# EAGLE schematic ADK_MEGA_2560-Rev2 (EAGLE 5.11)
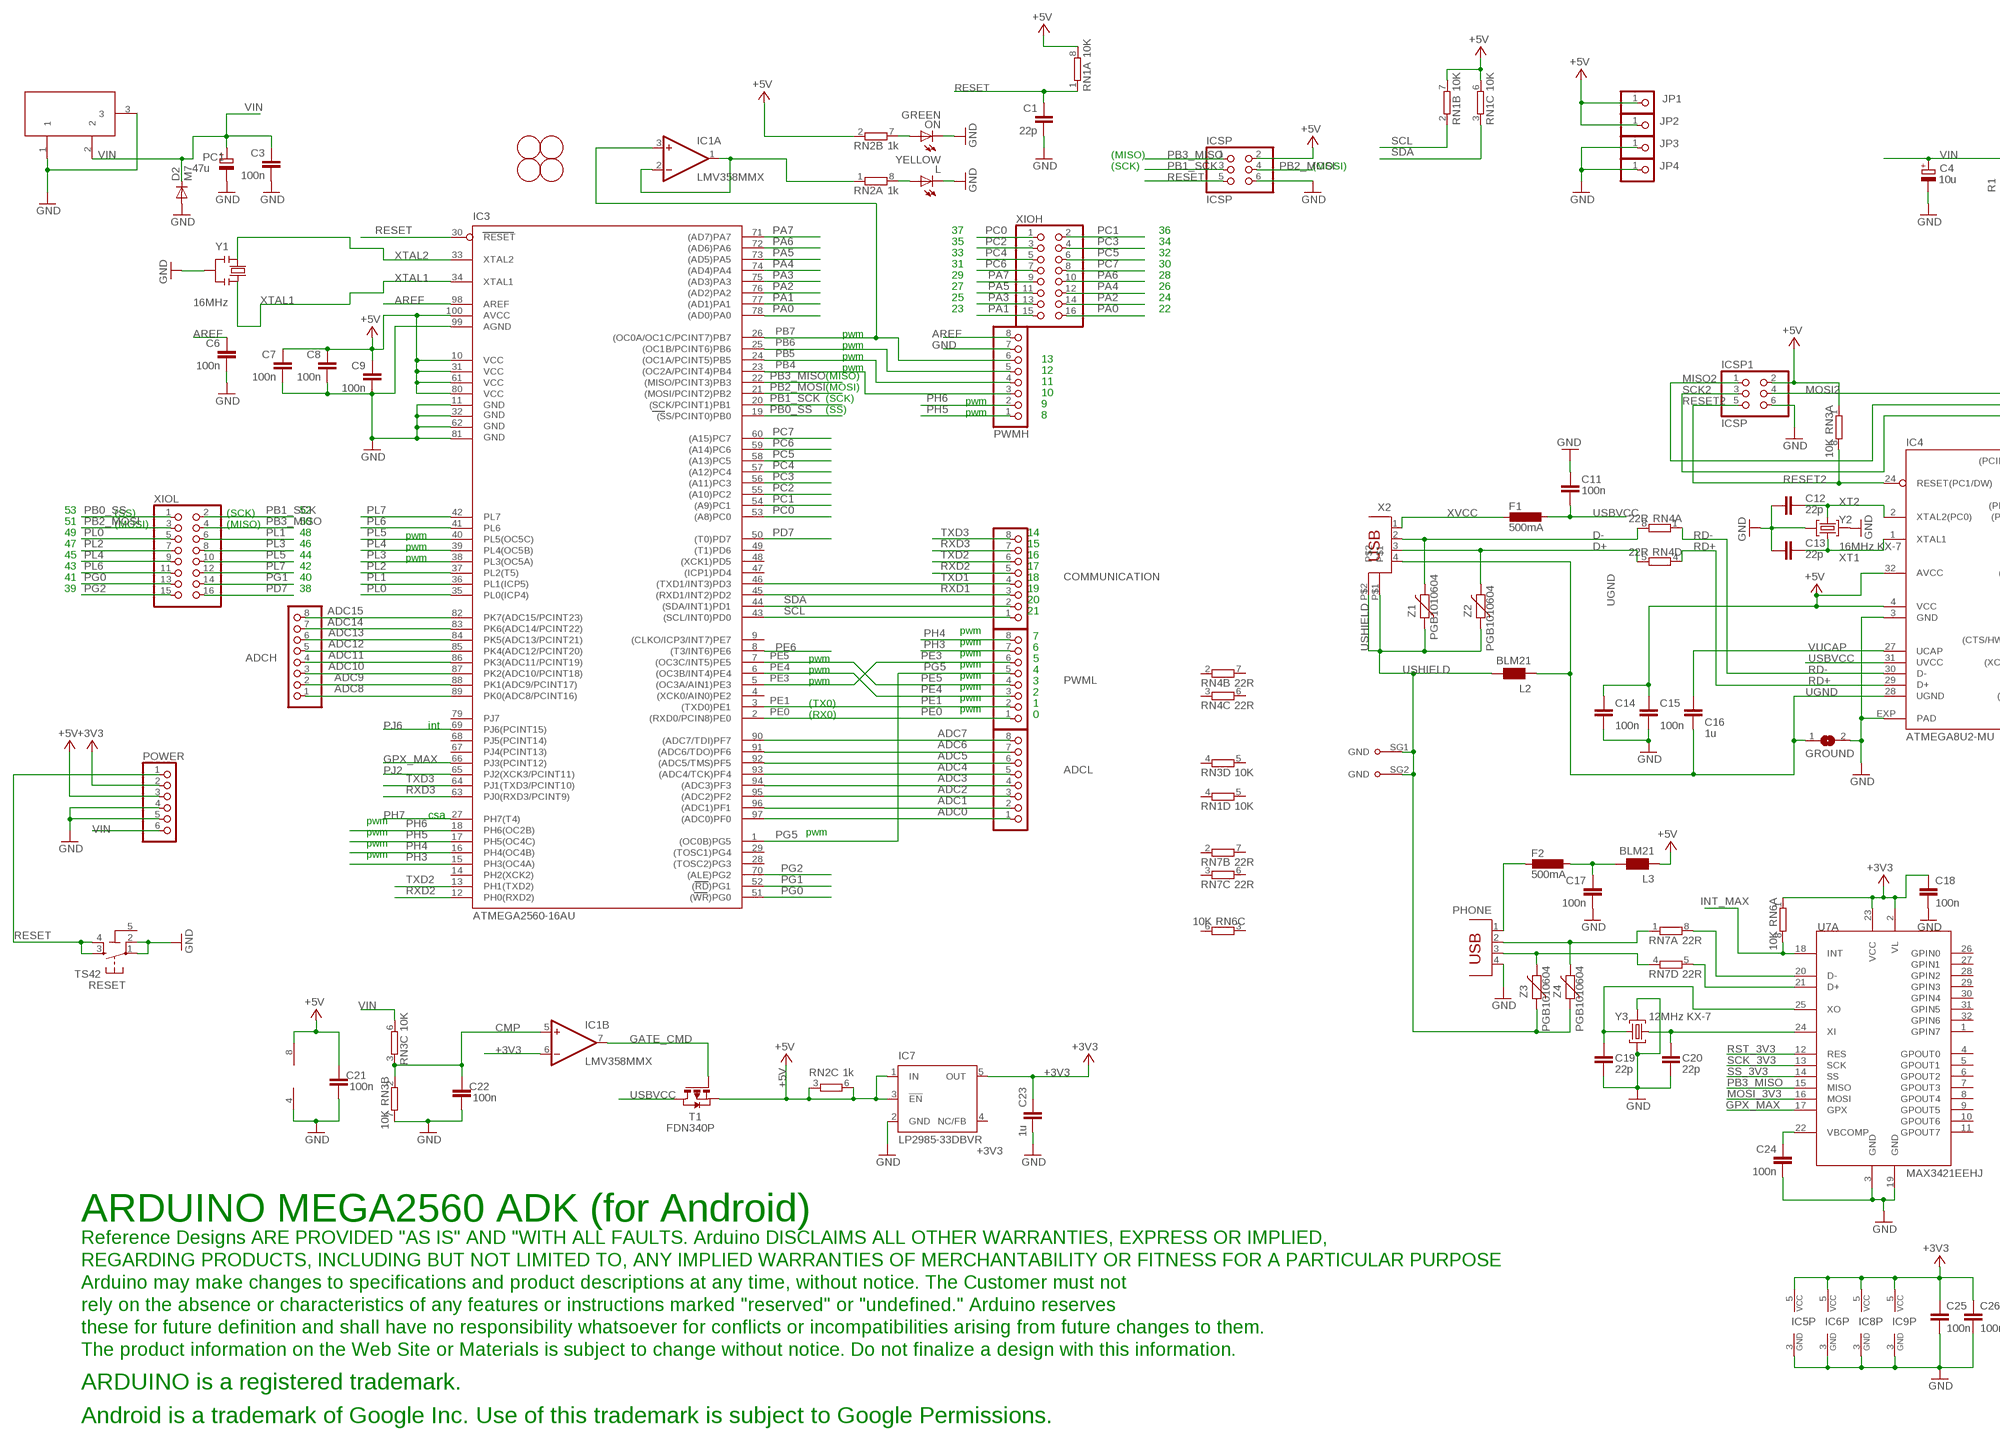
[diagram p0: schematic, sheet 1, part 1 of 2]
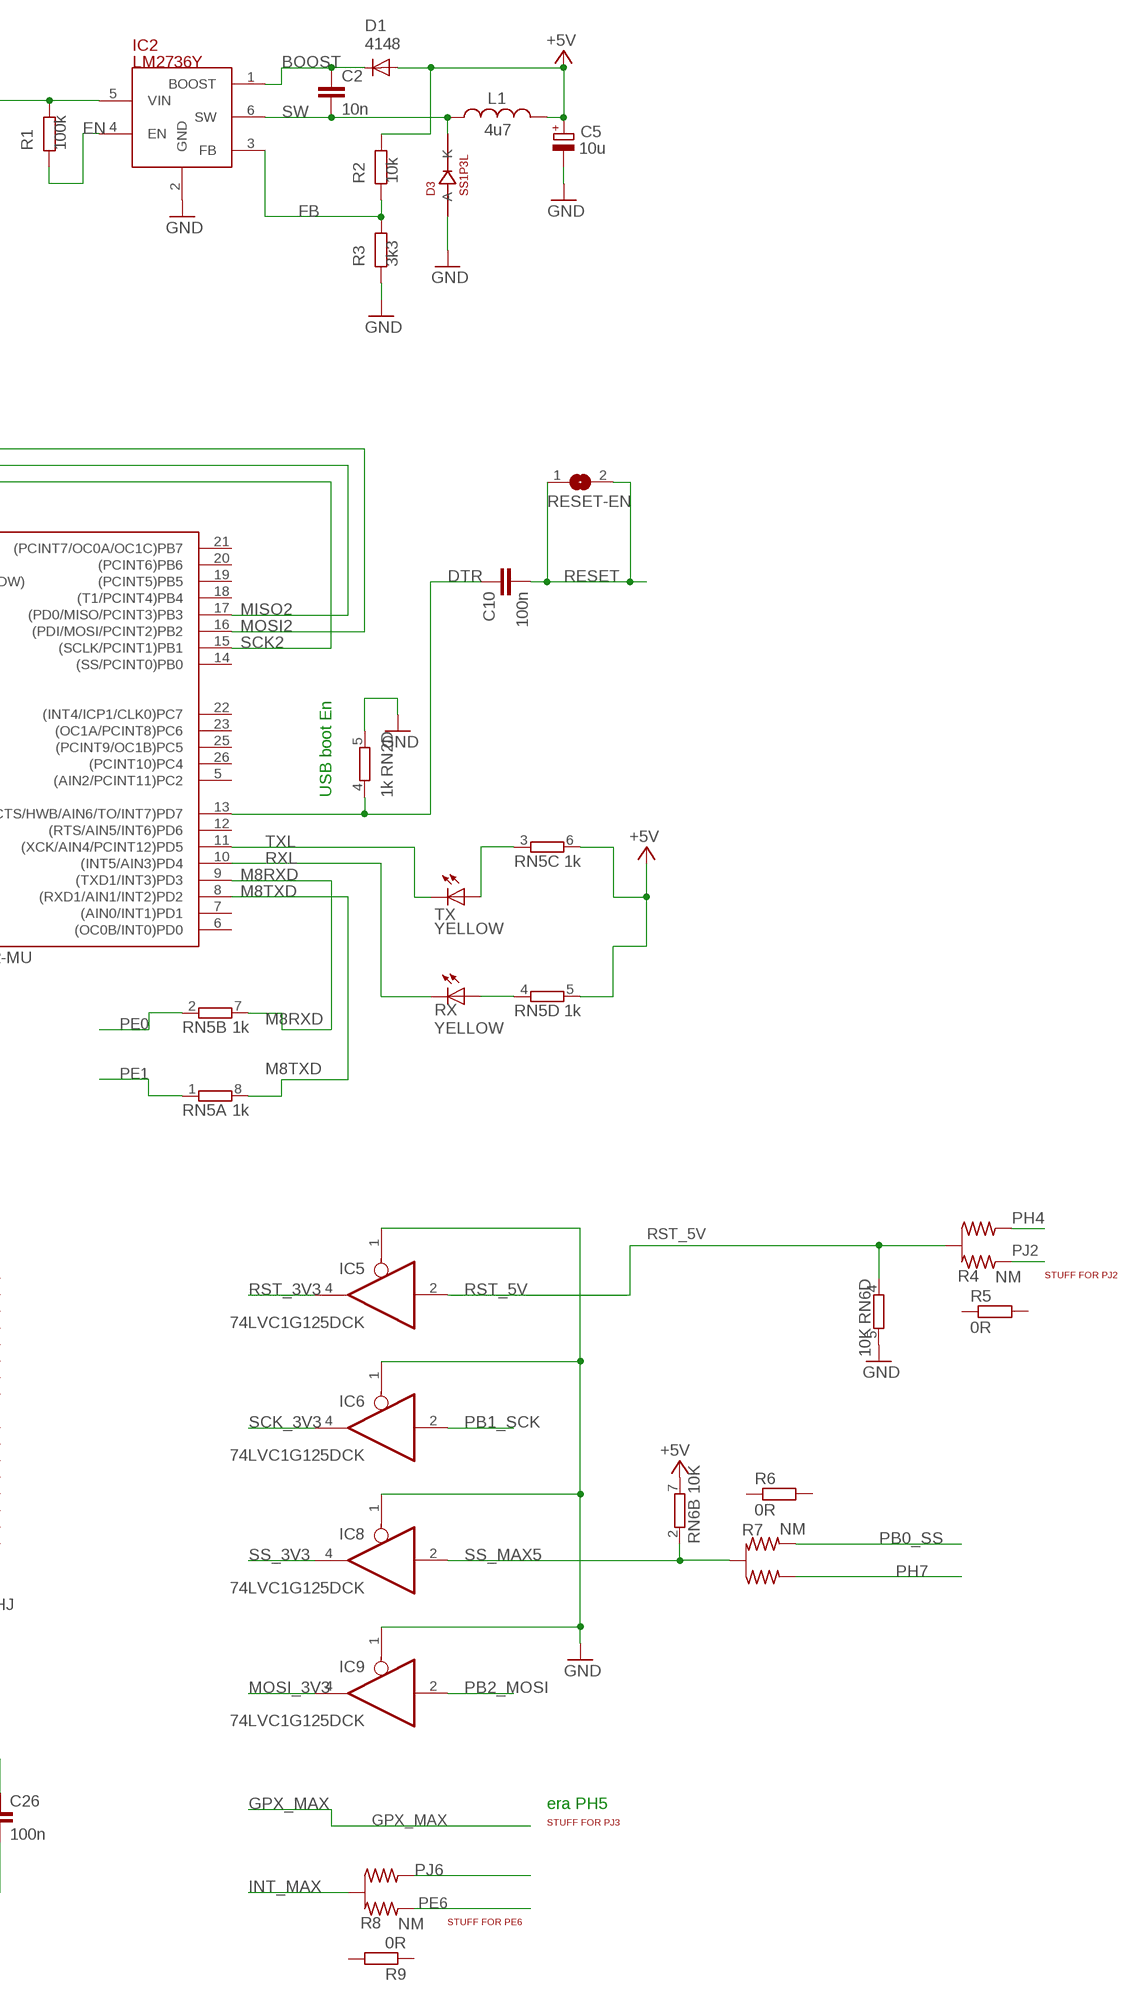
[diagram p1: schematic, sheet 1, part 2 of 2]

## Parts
ADCH  PINHD-1X8  [1X08]
ADCL  PINHD-1X8  [1X08]
C1  22p  C-EU0603-RND  [C0603-ROUND]
C2  10n  C-EUC0603  [C0603-ROUND]
C3  100n  C-EU0603-RND  [C0603-ROUND]
C4  10u  CPOL-EUSMCB  [SMC_B]
C5  10u  CPOL-EUSMCB  [SMC_B]
C6  100n  C-EU0603-RND  [C0603-ROUND]
C7  100n  C-EU0603-RND  [C0603-ROUND]
C8  100n  C-EU0603-RND  [C0603-ROUND]
C9  100n  C-EU0603-RND  [C0603-ROUND]
C10  100n  C-EU0603-RND  [C0603-ROUND]
C11  100n  C-EU0603-RND  [C0603-ROUND]
C12  22p  C-EU0603-RND  [C0603-ROUND]
C13  22p  C-EU0603-RND  [C0603-ROUND]
C14  100n  C-EU0603-RND  [C0603-ROUND]
C15  100n  C-EU0603-RND  [C0603-ROUND]
C16  1u  C-EU0603-RND  [C0603-ROUND]
C17  100n  C-EU0603-RND  [C0603-ROUND]
C18  100n  C-EU0603-RND  [C0603-ROUND]
C19  22p  C-EU0603-RND  [C0603-ROUND]
C20  22p  C-EU0603-RND  [C0603-ROUND]
C21  100n  C-EU0603-RND  [C0603-ROUND]
C22  100n  C-EU0603-RND  [C0603-ROUND]
C23  1u  C-EU0603-RND  [C0603-ROUND]
C24  100n  C-EU0603-RND  [C0603-ROUND]
C25  100n  C-EU0603-RND  [C0603-ROUND]
C26  100n  C-EU0603-RND  [C0603-ROUND]
COMMUNICATION  PINHD-1X8  [1X08]
D1  4148  DIODE-MINIMELF  [MINIMELF]
D2  M7  DIODE-SMB  [SMB]
D3  SS1P3L  [DO220AAL]
F1  500mA  L-EUL1812  [L1812]
F2  500mA  L-EUL1812  [L1812]
GROUND  SJ  [SJ]
IC1  LMV358MMX  [MSOP08]
IC2  LM2736Y  [SOT23-6]
IC3  ATMEGA2560-16AU  ATMEGA1280-16AU  [TQFP100]
IC4  ATMEGA8U2-MU  ATMEL_ATMEGA8U2-MU  [ATMEL_QFN32]
IC5  74LVC1G125DCK  [SC70-5]
IC6  74LVC1G125DCK  [SC70-5]
IC7  LP2985-33DBVR  TPS77033  [SOT23-DBV]
IC8  74LVC1G125DCK  [SC70-5]
IC9  74LVC1G125DCK  [SC70-5]
ICSP  ICSP  PINHD-2X3  [2X03]
ICSP1  ICSP  PINHD-2X3  [2X03]
JP1  PINHD-1X1  [1X01]
JP2  PINHD-1X1  [1X01]
JP3  PINHD-1X1  [1X01]
JP4  PINHD-1X1  [1X01]
L  YELLOW  LEDCHIP-LED0805  [CHIP-LED0805]
L1  4u7  L-USSRR0604  [SRR0604]
L2  BLM21  WE-CBF_0805  [0805]
L3  BLM21  WE-CBF_0805  [0805]
ON  GREEN  LEDCHIP-LED0805  [CHIP-LED0805]
PC1  47u  CPOL-EUSMCB  [SMC_B]
PHONE  PN87520  [PN87520]
POWER  PINHD-1X6  [1X06]
PWMH  PINHD-1X8  [1X08]
PWML  PINHD-1X8  [1X08]
R1  100k  R-EU_0603-RND  [R0603-ROUND]
R2  10k  R-EU_0603-RND  [R0603-ROUND]
R3  3k3  R-EU_0603-RND  [R0603-ROUND]
R4  NM  J0402  [J0402]
R5  0R  R-EU_R0402  [R0402]
R6  0R  R-EU_R0402  [R0402]
R7  NM  J0402  [J0402]
R8  NM  J0402  [J0402]
R9  0R  R-EU_R0402  [R0402]
RESET  TS42  [TS42]
RESET-EN  SJ  [SJ]
RN1  10K  4R-NCAT16  [CAT16]
RN2  1k  4R-NCAY16  [CAY16]
RN3  10K  4R-NCAT16  [CAT16]
RN4  22R  4R-NCAY16  [CAY16]
RN5  1k  4R-NCAY16  [CAY16]
RN6  10K  4R-NCAT16  [CAT16]
RN7  22R  4R-NCAY16  [CAY16]
RX  YELLOW  LEDCHIP-LED0805  [CHIP-LED0805]
T1  FDN340P  PMOSSOT23  [SOT-23]
TX  YELLOW  LEDCHIP-LED0805  [CHIP-LED0805]
U7A  MAX3421EEHJ  [TQFP32-05]
U$1  FIDUCIALMOUNT  [FIDUCIA-MOUNT]
U$2  FIDUCIALMOUNT  [FIDUCIA-MOUNT]
U$3  FIDUCIALMOUNT  [FIDUCIA-MOUNT]
U$4  FIDUCIALMOUNT  [FIDUCIA-MOUNT]
X1  DC21MMX  [DC-21MM]
X2  PN61729  [PN61729]
XIOH  PINHD-2X8  [2X08]
XIOL  PINHD-2X8  [2X08]
Y1  16MHz  RESONATORMU  [RESONATOR]
Y2  16MHz KX-7  CRYSTAL-3.2-2.5  [CRYSTAL-3.2-2.5]
Y3  12MHz KX-7  CRYSTAL-3.2-2.5  [CRYSTAL-3.2-2.5]
Z1  PGB1010604  VARISTORCN0603  [CT/CN0603]
Z2  PGB1010604  VARISTORCN0603  [CT/CN0603]
Z3  PGB1010604  VARISTORCN0603  [CT/CN0603]
Z4  PGB1010604  VARISTORCN0603  [CT/CN0603]

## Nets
+3V3 [power]: C18.1 C23.2 C25.1 C26.1 IC1.6(B:-IN) IC5.5(VCC) IC6.5(VCC) IC7.5(OUT) IC8.5(VCC) IC9.5(VCC) POWER.2 RN6.1 U7A.2(VL) U7A.23(VCC)
+5V [power usb]: C5.+ C7.1 C8.1 C9.1 C14.1 C15.1 C21.2 D1.A IC1.8(P:V+) IC3.10(VCC) IC3.31(VCC1) IC3.61(VCC2) IC3.80(VCC3) IC3.100(AVCC) IC4.4(VCC) IC4.32(AVCC) IC7.1(IN) IC7.3(!EN) ICSP1.2 ICSP.2 JP1.1 JP2.1 L1.P$2 L3.1 POWER.3 R2.1 RN1.6 RN1.7 RN1.8 RN2.2 RN2.3 RN2.6 RN3.1 RN5.5 RN5.6 RN6.7 T1.2(S)
ADC0: ADCL.1 IC3.97((ADC0)PF0)
ADC1: ADCL.2 IC3.96((ADC1)PF1)
ADC2: ADCL.3 IC3.95((ADC2)PF2)
ADC3: ADCL.4 IC3.94((ADC3)PF3)
ADC4: ADCL.5 IC3.93((ADC4/TCK)PF4)
ADC5: ADCL.6 IC3.92((ADC5/TMS)PF5)
ADC6: ADCL.7 IC3.91((ADC6/TDO)PF6)
ADC7: ADCL.8 IC3.90((ADC7/TDI)PF7)
ADC8: ADCH.1 IC3.89(PK0(ADC8/PCINT16))
ADC9: ADCH.2 IC3.88(PK1(ADC9/PCINT17))
ADC10: ADCH.3 IC3.87(PK2(ADC10/PCINT18))
ADC11: ADCH.4 IC3.86(PK3(ADC11/PCINT19))
ADC12: ADCH.5 IC3.85(PK4(ADC12/PCINT20))
ADC13: ADCH.6 IC3.84(PK5(ADC13/PCINT21))
ADC14: ADCH.7 IC3.83(PK6(ADC14/PCINT22))
ADC15: ADCH.8 IC3.82(PK7(ADC15/PCINT23))
AREF: C6.1 IC3.98(AREF) PWMH.8
BOOST: C2.1 D1.C IC2.1(BOOST)
CMP: C22.2 IC1.5(B:+IN) RN3.2 RN3.3
D+: RN4.5 X2.3 Z2.2
D-: RN4.8 X2.2 Z1.2
DTR: C10.1 IC4.13((CTS/HWB/AIN6/TO/INT7)PD7) RN2.4
EN: IC2.4(EN) R1.2
FB: IC2.3(FB) R2.2 R3.1
GATE_CMD: IC1.7(B:OUT) T1.3(G)
GND [gnd]: C1.2 C3.2 C4.- C5.- C6.2 C7.2 C8.2 C9.2 C11.2 C12.2 C13.2 C14.2 C15.2 C17.2 C18.2 C19.1 C20.1 C21.1 C22.1 C23.1 C24.2 C25.2 C26.2 D2.A D3.P$2(A) GROUND.2 IC1.4(P:V-) IC2.2(GND) IC3.11(GND) IC3.32(GND1) IC3.62(GND2) IC3.81(GND3) IC3.99(AGND) IC4.3(GND) IC4.EXP(PAD) IC5.1(OE) IC5.3(GND) IC6.1(OE) IC6.3(GND) IC7.2(GND) IC8.1(OE) IC8.3(GND) IC9.1(OE) IC9.3(GND) ICSP1.6 ICSP.6 JP3.1 JP4.1 L.C ON.C PC1.- PHONE.4 POWER.4 POWER.5 PWMH.7 R3.2 RESET.1 RESET.2 RN2.5 RN3.7 RN6.5 U7A.3(GND) U7A.19(GND) X1.1 X1.3 Y1.2 Y2.2(GND) Y2.4(GND) Y3.2(GND) Y3.4(GND)
GPX_MAX: IC3.66(PJ3(PCINT12)) U7A.17(GPX)
INT_MAX: R8.2(C) RN6.8 U7A.18(INT)
M8RXD: IC4.9((TXD1/INT3)PD3) RN5.7
M8TXD: IC4.8((RXD1/AIN1/INT2)PD2) RN5.8
MISO2: IC4.17((PD0/MISO/PCINT3)PB3) ICSP1.1
MOSI2: IC4.16((PDI/MOSI/PCINT2)PB2) ICSP1.4
MOSI_3V3: IC9.4(O) U7A.16(MOSI)
N$1: IC1.1(A:OUT) IC1.2(A:-IN) RN2.1
N$2: L.A RN2.8
N$3: ON.A RN2.7
N$10: PHONE.2 RN7.1 Z4.2
N$11: PHONE.3 RN7.4 Z3.2
N$12: RN7.8 U7A.20(D-)
N$13: RN7.5 U7A.21(D+)
N$14: F2.2 PHONE.1
N$15: C20.2 U7A.24(XI) Y3.1(C1)
N$16: C19.2 U7A.25(XO) Y3.3(C2)
N$18: C17.1 F2.1 L3.2
N$39: C24.1 U7A.22(VBCOMP)
N$54: RN5.4 RX.A
N$55: RN5.3 TX.A
PA0: IC3.78((AD0)PA0) XIOH.16
PA1: IC3.77((AD1)PA1) XIOH.15
PA2: IC3.76((AD2)PA2) XIOH.14
PA3: IC3.75((AD3)PA3) XIOH.13
PA4: IC3.74((AD4)PA4) XIOH.12
PA5: IC3.73((AD5)PA5) XIOH.11
PA6: IC3.72((AD6)PA6) XIOH.10
PA7: IC3.71((AD7)PA7) XIOH.9
PB0_SS: IC3.19((SS/PCINT0)PB0) R7.3 XIOL.1
PB1_SCK: IC3.20((SCK/PCINT1)PB1) IC6.2(I) ICSP.3 XIOL.2
PB2_MOSI: IC3.21((MOSI/PCINT2)PB2) IC9.2(I) ICSP.4 XIOL.3
PB3_MISO: IC3.22((MISO/PCINT3)PB3) ICSP.1 U7A.15(MISO) XIOL.4
PB4: IC3.23((OC2A/PCINT4)PB4) PWMH.3
PB5: IC3.24((OC1A/PCINT5)PB5) PWMH.4
PB6: IC3.25((OC1B/PCINT6)PB6) PWMH.5
PB7: IC1.3(A:+IN) IC3.26((OC0A/OC1C/PCINT7)PB7) PWMH.6
PC0: IC3.53((A8)PC0) XIOH.1
PC1: IC3.54((A9)PC1) XIOH.2
PC2: IC3.55((A10)PC2) XIOH.3
PC3: IC3.56((A11)PC3) XIOH.4
PC4: IC3.57((A12)PC4) XIOH.5
PC5: IC3.58((A13)PC5) XIOH.6
PC6: IC3.59((A14)PC6) XIOH.7
PC7: IC3.60((A15)PC7) XIOH.8
PD7: IC3.50((T0)PD7) XIOL.16
PE0: IC3.2((RXD0/PCIN8)PE0) PWML.1 RN5.2
PE1: IC3.3((TXD0)PE1) PWML.2 RN5.1
PE3: IC3.5((OC3A/AIN1)PE3) PWML.6
PE4: IC3.6((OC3B/INT4)PE4) PWML.3
PE5: IC3.7((OC3C/INT5)PE5) PWML.4
PE6: IC3.8((T3/INT6)PE6) R8.3
PG0: IC3.51((WR)PG0) XIOL.13
PG1: IC3.52((RD)PG1) XIOL.14
PG2: IC3.70((ALE)PG2) XIOL.15
PG5: IC3.1((OC0B)PG5) PWML.5
PH3: IC3.15(PH3(OC4A)) PWML.7
PH4: IC3.16(PH4(OC4B)) PWML.8 R4.1
PH5: IC3.17(PH5(OC4C)) PWMH.1
PH6: IC3.18(PH6(OC2B)) PWMH.2
PH7: IC3.27(PH7(T4)) R7.1
PJ2: IC3.65(PJ2(XCK3/PCINT11)) R4.3
PJ6: IC3.69(PJ6(PCINT15)) R8.1
PL0: IC3.35(PL0(ICP4)) XIOL.5
PL1: IC3.36(PL1(ICP5)) XIOL.6
PL2: IC3.37(PL2(T5)) XIOL.7
PL3: IC3.38(PL3(OC5A)) XIOL.8
PL4: IC3.39(PL4(OC5B)) XIOL.9
PL5: IC3.40(PL5(OC5C)) XIOL.10
PL6: IC3.41(PL6) XIOL.11
PL7: IC3.42(PL7) XIOL.12
RD+: IC4.29(D+) RN4.4
RD-: IC4.30(D-) RN4.1
RESET: C1.1 C10.2 IC3.30(RESET) ICSP.5 POWER.1 RESET-EN.1 RESET-EN.2 RESET.3 RESET.4 RN1.1
RESET2: IC4.24(RESET(PC1/DW)) ICSP1.5 RN3.8
RST_3V3: IC5.4(O) U7A.12(RES)
RST_5V: IC5.2(I) R4.2(C) RN6.4
RXD1: COMMUNICATION.3 IC3.45((RXD1/INT2)PD2)
RXD2: COMMUNICATION.5 IC3.12(PH0(RXD2))
RXD3: COMMUNICATION.7 IC3.63(PJ0(RXD3/PCINT9))
RXL: IC4.10((INT5/AIN3)PD4) RX.C
SCK2: IC4.15((SCLK/PCINT1)PB1) ICSP1.3
SCK_3V3: IC6.4(O) U7A.13(SCK)
SCL: COMMUNICATION.1 IC3.43((SCL/INT0)PD0) RN1.2
SDA: COMMUNICATION.2 IC3.44((SDA/INT1)PD1) RN1.3
SS_3V3: IC8.4(O) U7A.14(SS)
SS_MAX5: IC8.2(I) R7.2(C) RN6.2
SW [power]: C2.2 D3.P$1(K) IC2.6(SW) L1.P$1
TXD1: COMMUNICATION.4 IC3.46((TXD1/INT3)PD3)
TXD2: COMMUNICATION.6 IC3.13(PH1(TXD2))
TXD3: COMMUNICATION.8 IC3.64(PJ1(TXD3/PCINT10))
TXL: IC4.11((XCK/AIN4/PCINT12)PD5) TX.C
UGND [gnd]: C16.2 GROUND.1 IC4.28(UGND) L2.1 X2.4
USBVCC [power usb]: C11.1 F1.1 IC4.31(UVCC) T1.1(D)
USHIELD [gnd]: L2.2 PHONE.SG1(GND) PHONE.SG2(GND) X2.P$1 X2.P$2 Z1.1 Z2.1 Z3.1 Z4.1
VIN [power]: C3.1 C4.+ D2.C IC2.5(VIN) PC1.+ POWER.6 R1.1 RN3.6 X1.2
VUCAP: C16.1 IC4.27(UCAP)
XT1: C13.1 IC4.1(XTAL1) Y2.1(C1)
XT2: C12.1 IC4.2(XTAL2(PC0)) Y2.3(C2)
XTAL1: IC3.34(XTAL1) Y1.3
XTAL2: IC3.33(XTAL2) Y1.1
XVCC [power usb]: F1.2 X2.1
Unconnected: IC3.4((XCK0/AIN0)PE2) IC3.9((CLKO/ICP3/INT7)PE7) IC3.14(PH2(XCK2)) IC3.28((TOSC2)PG3) IC3.29((TOSC1)PG4) IC3.47((ICP1)PD4) IC3.48((XCK1)PD5) IC3.49((T1)PD6) IC3.67(PJ4(PCINT13)) IC3.68(PJ5(PCINT14)) IC3.79(PJ7) IC4.5((AIN2/PCINT11)PC2) IC4.6((OC0B/INT0)PD0) IC4.7((AIN0/INT1)PD1) IC4.12((RTS/AIN5/INT6)PD6) IC4.14((SS/PCINT0)PB0) IC4.18((T1/PCINT4)PB4) IC4.19((PCINT5)PB5) IC4.20((PCINT6)PB6) IC4.21((PCINT7/OC0A/OC1C)PB7) IC4.22((INT4/ICP1/CLK0)PC7) IC4.23((OC1A/PCINT8)PC6) IC4.25((PCINT9/OC1B)PC5) IC4.26((PCINT10)PC4) IC7.4(NC/FB) R5.1 R5.2 R6.1 R6.2 R9.1 R9.2 RN1.4 RN1.5 RN3.4 RN3.5 RN4.2 RN4.3 RN4.6 RN4.7 RN6.3 RN6.6 RN7.2 RN7.3 RN7.6 RN7.7 U7A.1(GPIN7) U7A.4(GPOUT0) U7A.5(GPOUT1) U7A.6(GPOUT2) U7A.7(GPOUT3) U7A.8(GPOUT4) U7A.9(GPOUT5) U7A.10(GPOUT6) U7A.11(GPOUT7) U7A.26(GPIN0) U7A.27(GPIN1) U7A.28(GPIN2) U7A.29(GPIN3) U7A.30(GPIN4) U7A.31(GPIN5) U7A.32(GPIN6)

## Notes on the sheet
- (MISO)
- (SCK) | (MOSI)
- 37 | 36
- 35 | 34
- 33 | 32
- 31 | 30
- 29 | 28
- 27 | 26
- 25 | 24
- 23 | 22
- pwm
- pwm
- pwm | 13
- pwm | 12
- (MISO)
- 11
- (MOSI)
- 10
- (SCK) | pwm
- 9
- (SS) | pwm
- 8
- 53 | (SS) | (SCK) | 52
- 51 | (MOSI) | (MISO) | 50
- 49 | 48 | pwm | 14
- 47 | 46 | pwm | 15
- 45 | 44 | pwm | 16
- 43 | 42 | 17
- 41 | 40 | 18
- 39 | 38 | 19
- 20
- 21
- USB boot En
- pwm
- 7
- pwm
- 6
- pwm
- pwm | 5
- pwm
- pwm | 4
- pwm
- pwm | 3
- pwm
- 2
- pwm
- (TX0) | 1
- pwm
- (RX0) | 0
- int
- csa
- pwm
- pwm | pwm
- pwm
- pwm
- STUFF FOR PJ2
- ARDUINO MEGA2560 ADK (for Android)
- Reference Designs ARE PROVIDED "AS IS" AND "WITH ALL FAULTS. Arduino DISCLAIMS ALL OTHER WARRANTIES, EXPRESS OR IMPLIED,
- REGARDING PRODUCTS, INCLUDING BUT NOT LIMITED TO, ANY IMPLIED WARRANTIES OF MERCHANTABILITY OR FITNESS FOR A PARTICULAR PURPOSE
- Arduino may make changes to specifications and product descriptions at any time, without notice. The Customer must not
- rely on the absence or characteristics of any features or instructions marked "reserved" or "undefined." Arduino reserves | era PH5
- STUFF FOR PJ3
- these for future definition and shall have no responsibility whatsoever for conflicts or incompatibilities arising from future changes to them.
- The product information on the Web Site or Materials is subject to change without notice. Do not finalize a design with this information.
- ARDUINO is a registered trademark. | STUFF FOR PE6
- Android is a trademark of Google Inc. Use of this trademark is subject to Google Permissions.

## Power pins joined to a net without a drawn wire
5-GND: RESET.5(5-GND)

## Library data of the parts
ADCH ADCL COMMUNICATION PWMH PWML = pinhead:PINHD-1X8: PIN HEADER
C1-C3 C6-C26 = SmartPrj:C-EU: CAPACITOR, European symbol
C4 C5 PC1 = rcl:CPOL-EU: POLARIZED CAPACITOR, European symbol
D1 D2 = diode:DIODE-: DIODE
D3 = SmartPrj:SS1P3L
F1 F2 = rcl:L-EU: INDUCTOR, European symbol
GROUND RESET-EN = jumper:SJ: SMD solder JUMPER
IC1 = linear:LMV358?*: Dual General Purpose, Low Voltage, Rail-to-Rail Output Operational Amplifiers Source: http://www.national.com/mpf/LM/LMV321.html http://www.national.com/dt/lmv_qual.pdf
IC2 = SmartPrj:LM2736Y
IC3 = atmel-2005:ATMEGA*: MICROCONTROLLER 64/128/256 Kbytes FLASH 4 Kbytes EEPROM 8 Kbytes SRAM 86 General Purpose I/O pins 12-channels16-bit PWM 4 x Serial USARTs 16-channels 10-bit A/D
IC4 = SmartPrj:ATMEL_ATMEGA8U2-MU
IC5 IC6 IC8 IC9 = 74xx-little-us:74*1G125: Single Bus Buffer Gate with 3-State Output
IC7 = texas:TPS770*: ULTRALOW-POWER 50-mA LOW-DROPOUT LINEAR REGULATORS 50-mA Low-Dropout Regulator Source: http://focus.ti.com/lit/ds/symlink/tps77001.pdf
ICSP ICSP1 = pinhead:PINHD-2X3: PIN HEADER
JP1-JP4 = pinhead:PINHD-1X1: PIN HEADER
L ON RX TX = led:LED: LED
L1 = SmartPrj:L-US: INDUCTOR, American symbol
L2 L3 = wuerth-elektronik:WE-CBF: SMD EMI Suppression Ferrite Beads
PHONE = con-berg:PN87520: BERG
POWER = pinhead:PINHD-1X6: PIN HEADER
R1-R3 R5 R6 R9 = SmartPrj:R-EU_: RESISTOR, European symbol
R4 R7 R8 = bibaja:J: Three terminal jumper made from two 0402, 0603, 0805, etc.
RESET = st-mod v1.4:TS42: TS42 Dongnan Electronics Tact switch VDC 12V - 50mA
RN1-RN7 = resistor-dil:4R-N: Array Chip Resistor Source: RS Component / Phycomp
T1 = zetex:PMOSSOT23: MOS FET
U7A = bibaja:MAX3421EE: MAX3421 SPI to USB Interface Chip
U$1-U$4 = SmartPrj:FIDUCIALMOUNT
X1 = powersupply:DC21MM
X2 = SmartPrj:PN61729: BERG USB connector
XIOH XIOL = pinhead:PINHD-2X8: PIN HEADER
Y1 = SmartPrj:RESONATOR
Y2 Y3 = SmartPrj:CRYSTAL-3.2-2.5
Z1-Z4 = varistor:VARISTOR: VARISTOR

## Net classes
0 default: width 0.203 mm, drill 0.406 mm, clearance 0.178 mm
1 power: width 0.305 mm, drill 0.406 mm, clearance 0.178 mm
2 gnd: width 0.305 mm, drill 0.406 mm, clearance 0.178 mm
3 power usb: width 0.508 mm, drill 0.406 mm, clearance 0.178 mm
